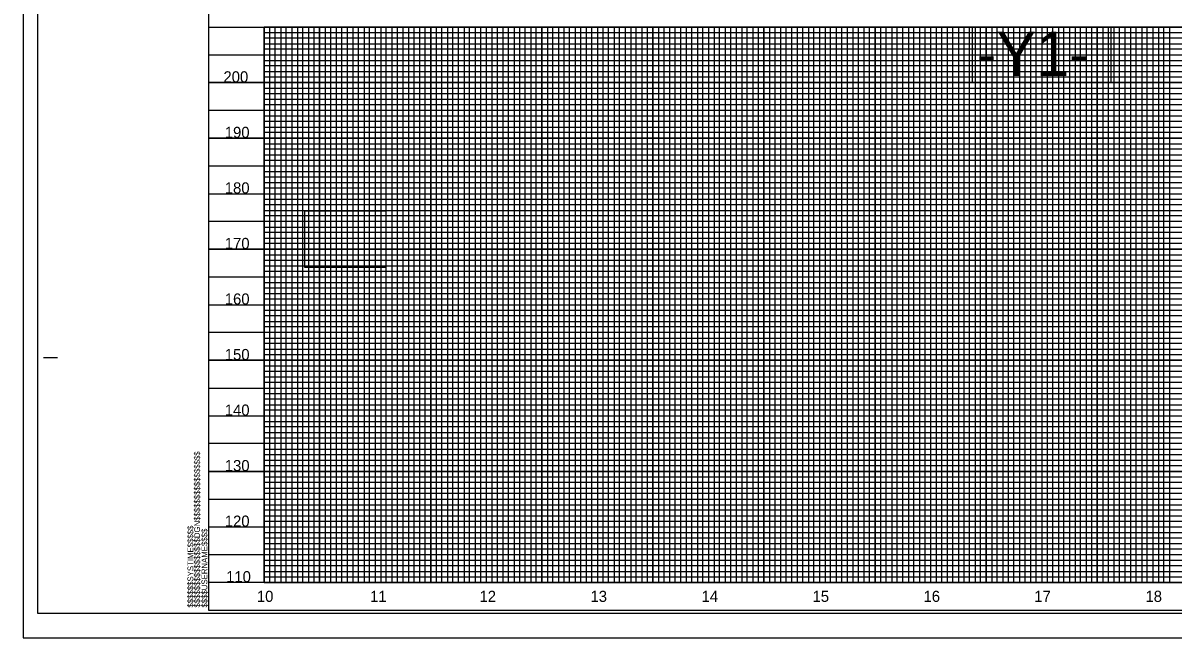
# Model space of a CAD drawing. Extents: x 1779926 to 1781626, y 618464 to 619564.
# Drawn here: x 1779926 to 1780961, y 618464 to 619018 of the extents above; entities that cross this region are included whole.
import ezdxf

# ---------------------------------------------------------------- set-up
doc = ezdxf.new("R2010")
doc.units = 0
for name, color, linetype in [('Exist Vertical Profile Horizontal Axis Label Major', 7, 'Continuous'), ('Exist Vertical Profile Vertical Axis Label', 7, 'Continuous'), ('Prop DSN Text', 7, 'Continuous'), ('Prop Grid Mask', 7, 'Continuous'), ('Sheet DOT Grid CELL', 7, 'Continuous'), ('Sheet Layout Profile Border Port 2', 7, 'Continuous'), ('Sheet Plot Border Inside CELL', 7, 'Continuous'), ('Sheet Plot Border Outside CELL', 7, 'Continuous'), ('Sheet Profile CELL', 7, 'Continuous'), ('Sheet Profile Grid Major CELL', 7, 'Continuous'), ('Sheet Profile Grid Middle CELL', 7, 'Continuous'), ('Sheet Profile Grid Minor CELL', 7, 'Continuous')]:
    doc.layers.add(name, color=color, linetype=linetype)

msp = doc.modelspace()

# ---------------------------------------------------------------- linework, layer by layer
at = {"layer": 'Prop Grid Mask'}
for points in [[(1780905.4, 619014.2), (1780780.5, 619014.2), (1780780.5, 618964.2), (1780905.4, 618964.2)], [(1780179.6, 618848.8), (1780252.6, 618848.8), (1780252.6, 618797.8), (1780179.6, 618797.8)]]:
    msp.add_lwpolyline(points, close=True, dxfattribs=at)
at = {"layer": 'Sheet DOT Grid CELL'}
for p, q in [((1780093, 619014.2), (1781592.8, 619014.2)), ((1780143, 619014.2), (1780143, 618514.2)), ((1780193, 619014.2), (1780193, 618514.2)), ((1780243, 619014.2), (1780243, 618514.2)), ((1780293, 619014.2), (1780293, 618514.2)), ((1780343, 619014.2), (1780343, 618514.2)), ((1780393, 619014.2), (1780393, 618514.2)), ((1780443, 619014.2), (1780443, 618514.2)), ((1780493, 619014.2), (1780493, 618514.2)), ((1780543, 619014.2), (1780543, 618514.2)), ((1780593, 619014.2), (1780593, 618514.2)), ((1780643, 619014.2), (1780643, 618514.2)), ((1780693, 619014.2), (1780693, 618514.2)), ((1780743, 619014.2), (1780743, 618514.2)), ((1780793, 619014.2), (1780793, 618514.2)), ((1780843, 619014.2), (1780843, 618514.2)), ((1780893, 619014.2), (1780893, 618514.2)), ((1780943, 619014.2), (1780943, 618514.2)), ((1780093, 618964.2), (1781592.8, 618964.2)), ((1780093, 618914.2), (1781592.8, 618914.2)), ((1780093, 618864.2), (1781592.8, 618864.2)), ((1780093, 618814.2), (1781592.8, 618814.2)), ((1780093, 618764.2), (1781592.8, 618764.2)), ((1780093, 618714.2), (1781592.8, 618714.2)), ((1780093, 618664.2), (1781592.8, 618664.2)), ((1780093, 618614.2), (1781592.8, 618614.2)), ((1780093, 618564.2), (1781592.8, 618564.2))]:
    msp.add_line(p, q, dxfattribs=at)
at = {"layer": 'Sheet Layout Profile Border Port 2'}
msp.add_lwpolyline([(1780143, 619014.2), (1781543, 619014.2), (1781543, 618514.2), (1780143, 618514.2)], close=True, dxfattribs=at)
msp.add_lwpolyline([(1781443, 619014.2), (1780143, 619014.2), (1780143, 618514.2), (1781543, 618514.2), (1781543, 619014.2)], dxfattribs=at)
at = {"layer": 'Sheet Plot Border Inside CELL'}
msp.add_lwpolyline([(1779939, 618486.6), (1781605.5, 618486.6), (1781605.5, 619541.7), (1779939, 619541.7)], close=True, dxfattribs=at)
at = {"layer": 'Sheet Plot Border Outside CELL'}
msp.add_lwpolyline([(1779926, 618464.2), (1781626, 618464.2), (1781626, 619564.2), (1779926, 619564.2)], close=True, dxfattribs=at)
at = {"layer": 'Sheet Profile CELL'}
for p, q in [((1780093, 619014.2), (1781593, 619014.2)), ((1779944.5, 618716.7), (1779957, 618716.7)), ((1781593, 618514.2), (1780093, 618514.2)), ((1780093, 618489.2), (1781593, 618489.2)), ((1780093, 618489.2), (1780093, 618489.2)), ((1780093, 618489.2), (1780093, 618489.2)), ((1780093, 618489.2), (1780093, 618489.2)), ((1780093, 618489.2), (1780093, 618489.2)), ((1780093, 618489.2), (1780093, 618489.2)), ((1780093, 618489.2), (1780093, 618489.2)), ((1780093, 618489.2), (1780093, 618489.2))]:
    msp.add_line(p, q, dxfattribs=at)
msp.add_lwpolyline([(1781593, 619539.2), (1780093, 619539.2), (1780093, 618489.2), (1781593, 618489.2)], close=True, dxfattribs=at)
msp.add_lwpolyline([(1780130.5, 618489.2), (1780130.5, 618489.2)], dxfattribs=at)
at = {"layer": 'Sheet Profile Grid Major CELL'}
for p, q in [((1780593, 619014.2), (1780643, 619014.2)), ((1780693, 619014.2), (1780743, 619014.2)), ((1780793, 619014.2), (1780843, 619014.2)), ((1780893, 619014.2), (1780943, 619014.2)), ((1780093, 618514.2), (1780093, 618514.2))]:
    msp.add_line(p, q, dxfattribs=at)
for points in [[(1780143, 619014.2), (1780143, 618514.2), (1780193, 618514.2), (1780193, 619014.2), (1780243, 619014.2), (1780243, 618514.2), (1780293, 618514.2), (1780293, 619014.2), (1780343, 619014.2), (1780343, 618514.2), (1780393, 618514.2), (1780393, 619014.2), (1780443, 619014.2), (1780443, 618514.2), (1780493, 618514.2), (1780493, 619014.2), (1780543, 619014.2), (1780543, 618514.2), (1780593, 618514.2), (1780593, 619014.2), (1780643, 619014.2), (1780643, 618514.2), (1780693, 618514.2), (1780693, 619014.2), (1780743, 619014.2), (1780743, 618514.2), (1780793, 618514.2), (1780793, 619014.2), (1780843, 619014.2), (1780843, 618514.2), (1780893, 618514.2), (1780893, 619014.2), (1780943, 619014.2), (1780943, 618514.2), (1780993, 618514.2)], [(1781593, 618964.2), (1780093, 618964.2)], [(1781593, 618914.2), (1780093, 618914.2), (1780093, 618864.2), (1781593, 618864.2)], [(1781593, 618814.2), (1780093, 618814.2), (1780093, 618764.2), (1781593, 618764.2)], [(1781593, 618714.2), (1780093, 618714.2), (1780093, 618664.2), (1781593, 618664.2)], [(1781593, 618614.2), (1780093, 618614.2), (1780093, 618614.2), (1780093, 618564.2), (1781593, 618564.2)], [(1781593, 618514.2), (1780093, 618514.2)]]:
    msp.add_lwpolyline(points, dxfattribs=at)
at = {"layer": 'Sheet Profile Grid Middle CELL'}
for points in [[(1780118, 619014.2), (1780168, 619014.2), (1780168, 618514.2), (1780218, 618514.2), (1780218, 619014.2), (1780268, 619014.2), (1780268, 618514.2), (1780318, 618514.2), (1780318, 619014.2), (1780368, 619014.2), (1780368, 618514.2), (1780418, 618514.2), (1780418, 619014.2), (1780468, 619014.2), (1780468, 618514.2), (1780518, 618514.2), (1780518, 619014.2), (1780568, 619014.2), (1780568, 618514.2), (1780618, 618514.2), (1780618, 619014.2), (1780668, 619014.2), (1780668, 618514.2), (1780718, 618514.2), (1780718, 618514.2), (1780718, 619014.2), (1780768, 619014.2), (1780768, 618514.2), (1780818, 618514.2), (1780818, 619014.2), (1780868, 619014.2), (1780868, 618514.2), (1780918, 618514.2), (1780918, 619014.2), (1780968, 619014.2)], [(1780093, 618989.2), (1781593, 618989.2)], [(1781593, 618939.2), (1780093, 618939.2), (1780093, 618889.2), (1781593, 618889.2)], [(1781593, 618839.2), (1780093, 618839.2), (1780093, 618789.2), (1781593, 618789.2)], [(1781593, 618739.2), (1780093, 618739.2), (1780093, 618689.2), (1781593, 618689.2)], [(1781593, 618639.2), (1780093, 618639.2), (1780093, 618589.2), (1781593, 618589.2)], [(1781593, 618539.2), (1780093, 618539.2)]]:
    msp.add_lwpolyline(points, dxfattribs=at)
at = {"layer": 'Sheet Profile Grid Minor CELL'}
for p, q in [((1780143, 619009.2), (1781543, 619009.2)), ((1781543, 619004.2), (1780143, 619004.2)), ((1780143, 618999.2), (1781543, 618999.2)), ((1781543, 618994.2), (1780143, 618994.2)), ((1780143, 618984.2), (1781543, 618984.2)), ((1781543, 618979.2), (1780143, 618979.2)), ((1780143, 618974.2), (1781543, 618974.2)), ((1781543, 618969.2), (1780143, 618969.2)), ((1780143, 618959.2), (1781543, 618959.2)), ((1781543, 618954.2), (1780143, 618954.2)), ((1780143, 618949.2), (1781543, 618949.2)), ((1781543, 618944.2), (1780143, 618944.2)), ((1780143, 618934.2), (1781543, 618934.2)), ((1781543, 618929.2), (1780143, 618929.2)), ((1780143, 618924.2), (1781543, 618924.2)), ((1781543, 618919.2), (1780143, 618919.2)), ((1780143, 618909.2), (1781543, 618909.2)), ((1781543, 618904.2), (1780143, 618904.2)), ((1780143, 618899.2), (1781543, 618899.2)), ((1781543, 618894.2), (1780143, 618894.2)), ((1780143, 618884.2), (1781543, 618884.2)), ((1781543, 618879.2), (1780143, 618879.2)), ((1780143, 618874.2), (1781543, 618874.2)), ((1781543, 618869.2), (1780143, 618869.2)), ((1780143, 618859.2), (1781543, 618859.2)), ((1781543, 618854.2), (1780143, 618854.2)), ((1780143, 618849.2), (1781543, 618849.2)), ((1781543, 618844.2), (1780143, 618844.2)), ((1780143, 618834.2), (1781543, 618834.2)), ((1781543, 618829.2), (1780143, 618829.2)), ((1780143, 618824.2), (1781543, 618824.2)), ((1781543, 618819.2), (1780143, 618819.3)), ((1780143, 618809.2), (1781543, 618809.2)), ((1781543, 618804.2), (1780143, 618804.2)), ((1780143, 618799.2), (1781543, 618799.2)), ((1781543, 618794.2), (1780143, 618794.2)), ((1780143, 618784.2), (1781543, 618784.2)), ((1781543, 618779.2), (1780143, 618779.2)), ((1780143, 618774.2), (1781543, 618774.2)), ((1781543, 618769.2), (1780143, 618769.2)), ((1780143, 618759.2), (1781543, 618759.2)), ((1781543, 618754.2), (1780143, 618754.2)), ((1780143, 618749.2), (1781543, 618749.2)), ((1781543, 618744.2), (1780143, 618744.2)), ((1780143, 618734.2), (1781543, 618734.2)), ((1781543, 618729.2), (1780143, 618729.2)), ((1780143, 618724.2), (1781543, 618724.2)), ((1781543, 618719.2), (1780143, 618719.2)), ((1780143, 618709.2), (1781543, 618709.2)), ((1781543, 618704.2), (1780143, 618704.2)), ((1780143, 618699.2), (1781543, 618699.2)), ((1781543, 618694.2), (1780143, 618694.2)), ((1780143, 618684.2), (1781543, 618684.2)), ((1781543, 618679.2), (1780143, 618679.2)), ((1780143, 618674.2), (1781543, 618674.2)), ((1781543, 618669.2), (1780143, 618669.2)), ((1780143, 618659.2), (1781543, 618659.2)), ((1781543, 618654.2), (1780143, 618654.2)), ((1780143, 618649.2), (1781543, 618649.2)), ((1781543, 618644.2), (1780143, 618644.2)), ((1780143, 618634.2), (1781543, 618634.2)), ((1781543, 618629.2), (1780143, 618629.2)), ((1780143, 618624.2), (1781543, 618624.2)), ((1781543, 618619.2), (1780143, 618619.2)), ((1780143, 618609.2), (1781543, 618609.2)), ((1781543, 618604.2), (1780143, 618604.2)), ((1780143, 618599.2), (1781543, 618599.2)), ((1781543, 618594.2), (1780143, 618594.2)), ((1780143, 618584.2), (1781543, 618584.2)), ((1781543, 618579.2), (1780143, 618579.2)), ((1780143, 618574.2), (1781543, 618574.2)), ((1781543, 618569.2), (1780143, 618569.2)), ((1780143, 618559.2), (1781543, 618559.2)), ((1781543, 618554.2), (1780143, 618554.2)), ((1780143, 618549.2), (1781543, 618549.2)), ((1781543, 618544.2), (1780143, 618544.2)), ((1780143, 618534.2), (1781543, 618534.2)), ((1781543, 618529.2), (1780143, 618529.2)), ((1780143, 618524.2), (1781543, 618524.2)), ((1780143, 618519.2), (1781543, 618519.2))]:
    msp.add_line(p, q, dxfattribs=at)
for points in [[(1780143, 619014.2), (1780148, 619014.2), (1780148, 618514.2), (1780153, 618514.2), (1780153, 619014.2), (1780158, 619014.2), (1780158, 618514.2), (1780163, 618514.2), (1780163, 619014.2), (1780173, 619014.2), (1780173, 618514.2), (1780178, 618514.2), (1780178, 619014.2), (1780183, 619014.2), (1780183, 618514.2), (1780188, 618514.2), (1780198, 618514.2), (1780203, 618514.2), (1780203, 619014.2), (1780208, 619014.2), (1780208, 618514.2), (1780213, 618514.2), (1780213, 619014.2), (1780223, 619014.2), (1780223, 618514.2), (1780228, 618514.2), (1780228, 619014.2), (1780233, 619014.2), (1780233, 618514.2), (1780238, 618514.2), (1780238, 619014.2), (1780248, 619014.2), (1780248, 618514.2), (1780253, 618514.2), (1780253, 619014.2), (1780258, 619014.2), (1780258, 618514.2), (1780263, 618514.2), (1780263, 619014.2), (1780273, 619014.2), (1780273, 618514.2), (1780278, 618514.2), (1780278, 619014.2), (1780283, 619014.2), (1780283, 618514.2), (1780288, 618514.2), (1780288, 619014.2), (1780298, 619014.2), (1780298, 618514.2), (1780303, 618514.2), (1780303, 619014.2), (1780308, 619014.2), (1780308, 618514.2), (1780313, 618514.2), (1780313, 619014.2), (1780323, 619014.2), (1780323, 618514.2), (1780328, 618514.2), (1780328, 619014.2), (1780333, 619014.2), (1780333, 618514.2), (1780338, 618514.2), (1780338, 619014.2), (1780348, 619014.2), (1780348, 618514.2), (1780353, 618514.2), (1780353, 619014.2), (1780358, 619014.2), (1780358, 618514.2)], [(1780188, 618514.2), (1780188, 619014.2), (1780198, 619014.2), (1780198, 618514.2)], [(1780358, 618514.2), (1780363, 618514.2), (1780363, 619014.2), (1780373, 619014.2), (1780373, 618514.2), (1780378, 618514.2), (1780378, 619014.2), (1780383, 619014.2), (1780383, 618514.2), (1780388, 618514.2), (1780388, 619014.2), (1780398, 619014.2), (1780398, 618514.2), (1780403, 618514.2), (1780403, 619014.2), (1780408, 619014.2), (1780408, 618514.2), (1780413, 618514.2), (1780413, 619014.2), (1780423, 619014.2), (1780423, 618514.2), (1780428, 618514.2), (1780428, 619014.2), (1780433, 619014.2), (1780433, 618514.2), (1780438, 618514.2), (1780438, 619014.2), (1780448, 619014.2), (1780448, 618514.2), (1780453, 618514.2), (1780453, 619014.2), (1780458, 619014.2), (1780458, 618514.2), (1780463, 618514.2), (1780463, 619014.2), (1780473, 619014.2), (1780473, 618514.2), (1780478, 618514.2), (1780478, 619014.2), (1780483, 619014.2), (1780483, 618514.2), (1780488, 618514.2), (1780488, 619014.2), (1780498, 619014.2), (1780498, 618514.2), (1780503, 618514.2), (1780503, 619014.2), (1780508, 619014.2), (1780508, 618514.2), (1780513, 618514.2), (1780513, 619014.2), (1780523, 619014.2), (1780523, 618514.2), (1780528, 618514.2), (1780528, 619014.2), (1780533, 619014.2), (1780533, 618514.2), (1780538, 618514.2), (1780538, 619014.2), (1780548, 619014.2), (1780548, 618514.2), (1780553, 618514.2), (1780553, 619014.2), (1780558, 619014.2), (1780558, 618514.2), (1780563, 618514.2), (1780563, 619014.2), (1780573, 619014.2), (1780573, 618514.2), (1780578, 618514.2), (1780578, 619014.2), (1780583, 619014.2), (1780583, 618514.2), (1780588, 618514.2), (1780588, 619014.2), (1780598, 619014.2), (1780598, 618514.2), (1780603, 618514.2), (1780603, 619014.2), (1780608, 619014.2), (1780608, 618514.2), (1780613, 618514.2), (1780613, 619014.2), (1780623, 619014.2), (1780623, 618514.2), (1780628, 618514.2), (1780628, 619014.2), (1780633, 619014.2), (1780633, 618514.2), (1780638, 618514.2), (1780638, 619014.2), (1780648, 619014.2), (1780648, 618514.2), (1780653, 618514.2), (1780653, 619014.2), (1780658, 619014.2), (1780658, 618514.2), (1780663, 618514.2), (1780663, 619014.2), (1780673, 619014.2)], [(1780673, 619014.2), (1780673, 618514.2), (1780678, 618514.2), (1780678, 619014.2), (1780683, 619014.2), (1780683, 618514.2), (1780688, 618514.2), (1780688, 619014.2), (1780698, 619014.2), (1780698, 618514.2), (1780703, 618514.2), (1780703, 619014.2), (1780708, 619014.2), (1780708, 618514.2), (1780713, 618514.2), (1780713, 619014.2), (1780723, 619014.2), (1780723, 618514.2), (1780728, 618514.2), (1780728, 619014.2), (1780733, 619014.2), (1780733, 618514.2), (1780738, 618514.2), (1780738, 619014.2), (1780748, 619014.2), (1780748, 618514.2), (1780753, 618514.2), (1780753, 619014.2), (1780758, 619014.2), (1780758, 618514.2), (1780763, 618514.2), (1780763, 619014.2), (1780773, 619014.2), (1780773, 618514.2), (1780778, 618514.2), (1780778, 619014.2), (1780783, 619014.2), (1780783, 618514.2), (1780788, 618514.2), (1780788, 619014.2), (1780798, 619014.2), (1780798, 618514.2), (1780798, 618514.2), (1780803, 618514.2), (1780803, 619014.2), (1780808, 619014.2), (1780808, 618514.2), (1780813, 618514.2), (1780813, 619014.2), (1780823, 619014.2), (1780823, 618514.2), (1780828, 618514.2), (1780828, 619014.2), (1780833, 619014.2), (1780833, 618514.2), (1780838, 618514.2), (1780838, 619014.2), (1780848, 619014.2), (1780848, 618514.2), (1780853, 618514.2), (1780853, 619014.2), (1780858, 619014.2), (1780858, 618514.2), (1780863, 618514.2), (1780863, 619014.2), (1780873, 619014.2), (1780873, 618514.2), (1780878, 618514.2), (1780878, 619014.2), (1780883, 619014.2), (1780883, 618514.2), (1780888, 618514.2), (1780888, 619014.2), (1780898, 619014.2), (1780898, 618514.2), (1780903, 618514.2), (1780903, 619014.2), (1780908, 619014.2), (1780908, 618514.2), (1780913, 618514.2), (1780913, 619014.2), (1780923, 619014.2), (1780923, 618514.2), (1780928, 618514.2), (1780928, 619014.2), (1780933, 619014.2), (1780933, 618514.2), (1780938, 618514.2), (1780938, 619014.2), (1780948, 619014.2), (1780948, 618514.2), (1780952.7, 618514.7), (1780953, 618514.2), (1780953, 619014.2), (1780958, 619014.2), (1780958, 618514.2), (1780963, 618514.2)]]:
    msp.add_lwpolyline(points, dxfattribs=at)

# ---------------------------------------------------------------- texts
at = {"layer": 'Exist Vertical Profile Horizontal Axis Label Major'}
for s, p in [('10', (1780136.5, 618496.7)), ('11', (1780238.4, 618496.7)), ('12', (1780336.9, 618496.7)), ('13', (1780436.8, 618496.7)), ('14', (1780536.8, 618496.7)), ('15', (1780636.7, 618496.7)), ('16', (1780736.6, 618496.7)), ('17', (1780836.3, 618496.7)), ('18', (1780936.4, 618496.7))]:
    msp.add_text(s, height=10, dxfattribs=at).set_placement(p)
at = {"layer": 'Exist Vertical Profile Vertical Axis Label'}
for s, p in [('200', (1780106.4, 618964.4)), ('190', (1780107.6, 618914.4)), ('180', (1780107.6, 618864.4)), ('170', (1780107.6, 618814.4)), ('160', (1780107.6, 618764.4)), ('150', (1780107.6, 618714.4)), ('140', (1780107.6, 618664.4)), ('130', (1780107.6, 618614.4)), ('120', (1780107.6, 618564.4)), ('110', (1780108.8, 618514.4))]:
    msp.add_text(s, height=10, dxfattribs=at).set_placement(p)
at = {"layer": 'Prop DSN Text'}
msp.add_text('-Y1-', height=40, dxfattribs=at).set_placement((1780784.4, 618970.1))
at = {"layer": 'Sheet Profile CELL'}
for s, p in [('$$$$$$$$$$$$$$$$DGN$$$$$$$$$$$$$$$$', (1780085.3, 618491.6)), ('$$$$$$SYSTIME$$$$$', (1780079.3, 618491.6)), ('$$$$USERNAME$$$$', (1780091.9, 618491.6))]:
    msp.add_text(s, height=5.25, rotation=90, dxfattribs=at).set_placement(p)

doc.saveas('drawing.dxf')
